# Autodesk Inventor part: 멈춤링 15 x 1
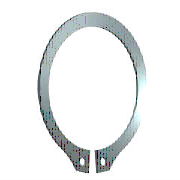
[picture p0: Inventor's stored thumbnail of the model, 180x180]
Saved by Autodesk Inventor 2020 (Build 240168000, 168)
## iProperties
IsCustomPart: 1
Created: 2012-02
Part Number: 멈춤링 15 x 1
Material: 강철, 연강
Description: 리테이닝 링(C형)
Document SubType Name: Modeling
Standard: KS B 1336
Designer: mduedu
Standards Organization: KS
Language: ko-KR
Size Designation: 15 x 1
Categories: <MemberInstance><Categories><Category DisplayName="샤프트 부품" InternalName="7f7aeb1f-a693-4053-b835-cee3144e0d98" Mnemonic="SHFT"><Category DisplayName="써클립" Inter
Density: 1 g/cm^3
Appearance: 파란색 - 벽 페인트 - 광택
Author: mduedu
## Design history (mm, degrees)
sketch "스케치1"
  geometry: L1 (-6, 0)-(6, 0) reference; L2 (0, 20.189)-(0, -80.536) reference; L3 (-48.09, 0)-(48.09, 0) reference; L4 (-0.425, -14.637)-(-0.425, -18.137); L5 (-0.425, -6.54)-(-0.425, -13.29); L6 (-2.795, 2.1)-(3.672, 2.1); L7 (0.425, -6.54)-(0.425, -13.29); L8 (0.425, -14.637)-(0.425, -18.137); C1 r 0.85 at (-1.7, -16.283); C2 r 0.85 at (1.7, -16.283); A1 r 7.15 centre (0, -7.5) between (0.425, -14.637) and (-0.425, -14.637); A2 r 9.075 centre (0, -6.975) between (4.291, -14.971) and (-4.291, -14.971); A3 r 10.646 centre (0, -7.5) between (-2.023, -17.952) and (-0.425, -18.137); A4 r 1.7 centre (-1.7, -16.283) between (-3.397, -16.376) and (-2.023, -17.952); A5 r 1.7 centre (-5.095, -16.469) between (-3.397, -16.376) and (-4.291, -14.971); A6 r 1.7 centre (5.095, -16.469) between (4.291, -14.971) and (3.397, -16.376); A7 r 1.7 centre (1.7, -16.283) between (2.023, -17.952) and (3.397, -16.376); A8 r 10.646 centre (0, -7.5) between (0.425, -18.137) and (2.023, -17.952)
  constraints: 16 point on circle, 12 end point, 10 centre point, 9 symmetric about line, 5 point on line, 4 tangent, 3 coincident, 2 horizontal, 1 perpendicular, 1 vertical, 5 other
  dimensions: "d0" = 14.3 diameter of A1 (= ND); "d1" = 3.5 distance of L4.end L4.start (= SRB2); "d6" = 0.425 distance between parallel lines of L2 L5 (= 0.25 x SD5); "d7" = 2.1 distance between parallel lines of L6 L3 (= SRB1); "d8" = 0.525 distance of A1.centre A2.centre (= 0.25 x SRB1); "d9" = 1.7 radius of A4 (= SD5); "d10" = 1.7 radius of A5 (= SD5); "d11" = 1.275 distance from line of L4 A4.centre (= 0.75 x SD5); "d12" = 1.7 diameter of C1 (= SD5); "d13" = 1.7 diameter of C2 (= SD5); "d14" = 7.5 distance from line of A1.centre L1 (= 0.5 x WD)
extrude "본체" new body sketch "스케치1" distance "d2" = 1 (= SD); taper "d3" = 0 deg
workaxis "Work Axis1"
workplane "Work Plane1"
body "Solid1"
other parameters: "WD" = 15 (= WDMIN) [user parameter; used in 1 equation term], "SD" = 1 [user parameter; used in 1 equation term], "SRB1" = 2.1 [user parameter; used in 2 equation terms], "ND" = 14.3 [user parameter; used in 1 equation term], "SRB2" = 3.5 [user parameter; used in 1 equation term], "SD5" = 1.7 [user parameter; used in 6 equation terms], "d15" = 0, "d16" = 0, "d17" = 0, "d41" = 0, "d42" = 0, "WDMIN" = 15 [user parameter; used in 1 equation term], "SD3" = 13.8 [user parameter], "WDMAX" = 16 [user parameter]
